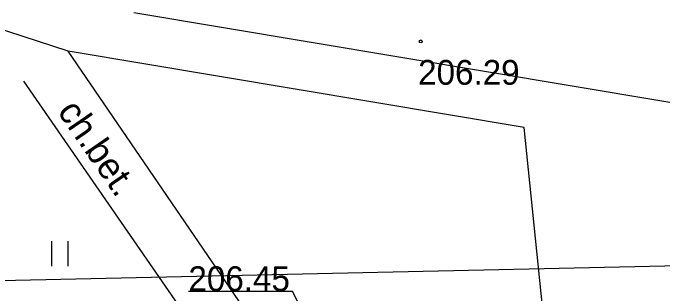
# Model space of a CAD drawing. Extents: x 6512606 to 6513006, y 6022524 to 6022728.
# Drawn here: x 6512764.26 to 6512783.87, y 6022694.12 to 6022702.59 of the extents above; entities that cross this region are included whole.
import ezdxf

# ---------------------------------------------------------------- set-up
doc = ezdxf.new("R2010")
doc.units = 0
for name, color, linetype in [('433-Chodnik', 7, 'Continuous'), ('940-Trawnik symb. poj.', 7, 'Continuous'), ('chodnik (powierzchnia)', 7, 'Continuous'), ('Default', 7, 'Continuous'), ('Obszar opracowania', 7, 'Continuous'), ('punkt o określonej wysokości (sieć elektroenergetyczna)-Atr2', 7, 'Continuous'), ('punkt wysokościowy sztuczny', 7, 'Continuous'), ('punkt wysokościowy sztuczny-Atr2', 7, 'Continuous')]:
    doc.layers.add(name, color=color, linetype=linetype)

# ---------------------------------------------------------------- blocks, each defined once
blk = doc.blocks.new('940P')
at = {"layer": 'Default'}
for p, q in [((-2.5, -3.75), (-2.5, 3.75)), ((2.5, -3.75), (2.5, 3.75))]:
    blk.add_line(p, q, dxfattribs=at)
blk = doc.blocks.new('PW02')
at = {"layer": 'Default'}
blk.add_circle((0, 0), 0.45, dxfattribs=at)

msp = doc.modelspace()

# ---------------------------------------------------------------- linework, layer by layer
at = {"layer": 'chodnik (powierzchnia)'}
for points in [[(6512790.1, 6022697.24), (6512786.51, 6022699.48), (6512767.913, 6022702.592)], [(6512780.55, 6022688.53), (6512780.6, 6022690.36), (6512779.7, 6022699.13), (6512765.93, 6022701.44), (6512762.734, 6022702.478)], [(6512764.58, 6022700.53), (6512771.43, 6022690.61), (6512771.38, 6022688.54), (6512772.96, 6022688.47), (6512773, 6022691.08), (6512765.93, 6022701.44)]]:
    msp.add_lwpolyline(points, dxfattribs=at)
at = {"layer": 'Obszar opracowania'}
msp.add_lwpolyline([(6512710.98, 6022693.84), (6512748.35, 6022694.16), (6512798.11, 6022695.25), (6512807.47, 6022695.46), (6512809.66, 6022606.87), (6512863.71, 6022622.03), (6512875.13, 6022581.36), (6512755.22, 6022535.25), (6512691.61, 6022568.03), (6512709.16, 6022605.16)], close=True, dxfattribs=at)
at = {"layer": 'punkt o określonej wysokości (sieć elektroenergetyczna)-Atr2'}
msp.add_lwpolyline([(6512775.84, 6022688.03), (6512772.7, 6022694.17), (6512769.559, 6022694.17)], dxfattribs=at)

# ---------------------------------------------------------------- block references
at = {"layer": '940-Trawnik symb. poj.', "xscale": 0.1, "yscale": 0.10000000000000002}
msp.add_blockref('940P', (6512765.68, 6022695.31), dxfattribs=at)
at = {"layer": 'punkt wysokościowy sztuczny', "xscale": 0.1, "yscale": 0.10000000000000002}
msp.add_blockref('PW02', (6512776.58, 6022701.73), dxfattribs=at)

# ---------------------------------------------------------------- texts
at = {"layer": '433-Chodnik'}
msp.add_text('ch.bet.', height=0.8, rotation=304.626, dxfattribs=at).set_placement((6512765.58, 6022699.61))
at = {"layer": 'punkt o określonej wysokości (sieć elektroenergetyczna)-Atr2'}
msp.add_text('206.45', height=0.75, dxfattribs=at).set_placement((6512769.559, 6022694.178))
at = {"layer": 'punkt wysokościowy sztuczny-Atr2'}
msp.add_text('206.29', height=0.75, dxfattribs=at).set_placement((6512776.5, 6022700.42))

doc.saveas('drawing.dxf')
